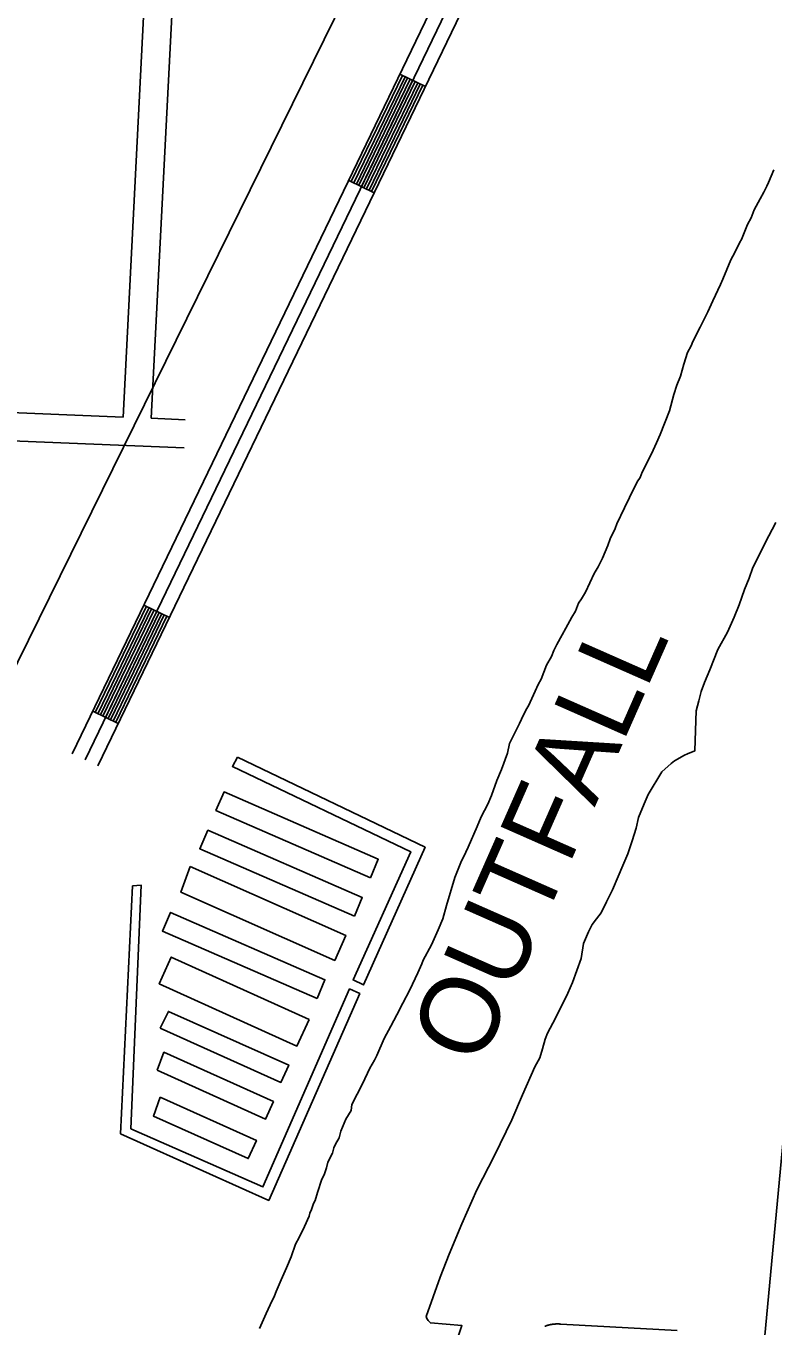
# Model space of a CAD drawing. Extents: x 3683402 to 3721514, y 487807 to 513565.
# Drawn here: x 3696820 to 3697613, y 500906 to 502284 of the extents above; entities that cross this region are included whole.
import ezdxf

# ---------------------------------------------------------------- set-up
doc = ezdxf.new("R2010")
doc.units = 0
for name, color, linetype in [('V-BLDG-OTLN', 7, 'Continuous'), ('V-RIVR-IDEN', 7, 'Continuous'), ('V-ROAD-CNTR', 7, 'Continuous'), ('V-TOPO-BNDY', 7, 'Continuous'), ('V-TOPO-SHOR', 7, 'Continuous')]:
    doc.layers.add(name, color=color, linetype=linetype)

msp = doc.modelspace()

# ---------------------------------------------------------------- linework, layer by layer
at = {"layer": 'V-BLDG-OTLN'}
for points in [[(3697044.7, 501508.9), (3697243.8, 501413.3), (3697178.5, 501267.3), (3697167.5, 501272.5), (3697228.6, 501408.5), (3697039.5, 501499)], [(3697185.9, 501380.9), (3697021.9, 501452.4), (3697030.5, 501472), (3697194.2, 501400.6)], [(3697168.9, 501340.2), (3697004.8, 501411.7), (3697013.4, 501431.3), (3697177.1, 501359.9)], [(3696994.7, 501392.9), (3697159.7, 501319.7), (3697147.9, 501293.2), (3696984.8, 501365.6)], [(3696933.5, 501372.3), (3696942.8, 501372.9), (3696931.8, 501114.8), (3697071.7, 501053.1), (3697163.8, 501263), (3697174.5, 501258), (3697078, 501038.7), (3696920.8, 501109.4)], [(3697129.3, 501252.9), (3696965.2, 501324.4), (3696973.8, 501344.1), (3697137.6, 501272.7)], [(3697120.8, 501230.5), (3697107.8, 501202.4), (3696961.8, 501268.5), (3696974.6, 501296.8)], [(3696962.7, 501221.3), (3696971.6, 501239.2), (3697099.1, 501182.2), (3697090.9, 501163.9)], [(3696959.5, 501176.7), (3696966.7, 501195.9), (3697082.9, 501143.6), (3697074.6, 501124.9)], [(3696962.8, 501148.1), (3697064.9, 501102.3), (3697056.3, 501083.1), (3696955.7, 501128.2)]]:
    msp.add_lwpolyline(points, close=True, dxfattribs=at)
at = {"layer": 'V-ROAD-CNTR'}
for p, q in [((3697217, 502233.1), (3697244.1, 502220.1)), ((3697162.8, 502120.5), (3697189.8, 502107.5)), ((3696945.6, 501670.1), (3696972.6, 501657.1)), ((3696891.3, 501557.5), (3696918.3, 501544.5))]:
    msp.add_line(p, q, dxfattribs=at)
for points in [[(3696869.6, 501512.5), (3697877.2, 503602.1)], [(3697897, 503608.5), (3696883.1, 501506)], [(3696896.6, 501499.5), (3697901.8, 503584.1)], [(3696980.5, 502990.5), (3696923.4, 501869.4)], [(3696977.2, 502337.1), (3696953.4, 501868.2)], [(3697165.5, 502119.2), (3697219.7, 502231.8)], [(3697168.2, 502117.9), (3697222.5, 502230.5)], [(3697170.9, 502116.6), (3697225.2, 502229.2)], [(3697173.6, 502115.3), (3697227.9, 502227.9)], [(3697176.3, 502114), (3697230.6, 502226.6)], [(3697179, 502112.7), (3697233.3, 502225.3)], [(3697181.7, 502111.4), (3697236, 502224)], [(3697184.4, 502110.1), (3697238.7, 502222.7)], [(3697187.1, 502108.8), (3697241.4, 502221.4)], [(3696923.4, 501869.4), (3696693, 501878.8)], [(3696989.4, 501866.7), (3696953.4, 501868.2)], [(3696988.2, 501836.8), (3696691.5, 501848.9)], [(3697685, 501758.1), (3697582.8, 500665.8)], [(3696894, 501556.2), (3696948.3, 501668.8)], [(3696896.7, 501554.9), (3696951, 501667.5)], [(3696899.4, 501553.6), (3696953.7, 501666.2)], [(3696902.1, 501552.3), (3696956.4, 501664.9)], [(3696904.8, 501551), (3696959.1, 501663.6)], [(3696907.5, 501549.7), (3696961.8, 501662.3)], [(3696910.2, 501548.4), (3696964.5, 501661)], [(3696912.9, 501547.1), (3696967.2, 501659.7)], [(3696915.6, 501545.8), (3696969.9, 501658.4)], [(3697370.7, 500905.3), (3697371.4, 500905.5), (3697372.1, 500905.8), (3697372.7, 500906), (3697373.4, 500906.2), (3697374.1, 500906.4), (3697374.8, 500906.5), (3697375.5, 500906.7), (3697376.2, 500906.8), (3697376.9, 500907), (3697377.6, 500907.1), (3697378.2, 500907.2), (3697378.9, 500907.3), (3697379.7, 500907.4), (3697380.4, 500907.5), (3697381.1, 500907.6), (3697381.8, 500907.6), (3697382.5, 500907.7), (3697383.2, 500907.7), (3697383.9, 500907.7), (3697384.6, 500907.7), (3697385.3, 500907.7), (3697386.1, 500907.7), (3697386.7, 500907.6), (3697387.4, 500907.6), (3697387.8, 500907.6), (3697511.2, 500900.9)]]:
    msp.add_lwpolyline(points, dxfattribs=at)
at = {"layer": 'V-TOPO-BNDY'}
msp.add_line((3697199.9, 502398), (3695552.8, 499054.3), dxfattribs=at)
at = {"layer": 'V-TOPO-SHOR'}
for points in [[(3697331.1, 501513), (3697333.5, 501523.2), (3697343.8, 501544.4), (3697346.2, 501549.1), (3697351, 501559.3), (3697353.4, 501563.2), (3697360.5, 501578.9), (3697363.7, 501586), (3697366.9, 501591.4), (3697372.5, 501606.3), (3697378, 501615.7), (3697380.4, 501622), (3697383.6, 501628.3), (3697389.2, 501638.5), (3697393.1, 501645.5), (3697399.5, 501657.3), (3697403.4, 501663.6), (3697406.6, 501672.2), (3697409.8, 501676.9), (3697413.8, 501683.9), (3697423.3, 501703.5), (3697427.3, 501710.6), (3697432.1, 501720), (3697437.6, 501733.3), (3697440, 501740.4), (3697445.6, 501751.4), (3697447.2, 501756.1), (3697455.2, 501773.3), (3697460.7, 501784.3), (3697468.7, 501800.8), (3697471.8, 501805.5), (3697474.2, 501811), (3697483.8, 501830.6), (3697489.3, 501842.3), (3697493.3, 501850.9), (3697502.9, 501876), (3697507.7, 501893.3), (3697510.9, 501903.5), (3697514.9, 501912.9), (3697518.1, 501925.5), (3697522.1, 501938), (3697526.1, 501945.1), (3697527.7, 501949.8), (3697535.6, 501964.7), (3697543.6, 501981.2), (3697549.2, 501992.9), (3697557.1, 502010.2), (3697559.5, 502015.7), (3697568.3, 502036.1), (3697572.2, 502043.9), (3697577.8, 502054.9), (3697579.4, 502058), (3697585.8, 502073.7), (3697589.7, 502080.7), (3697592.9, 502089.4), (3697599.3, 502101.1), (3697603.3, 502108.2), (3697606.4, 502114.5), (3697608, 502118.4), (3697613.6, 502131.7)], [(3697613.6, 502131.7), (3697608, 502118.4), (3697606.4, 502114.5), (3697603.3, 502108.2), (3697599.3, 502101.1), (3697592.9, 502089.4), (3697589.7, 502080.7), (3697585.8, 502073.7), (3697579.4, 502058), (3697577.8, 502054.9), (3697572.2, 502043.9), (3697568.3, 502036.1), (3697559.5, 502015.7), (3697557.1, 502010.2), (3697549.2, 501992.9), (3697543.6, 501981.2), (3697535.6, 501964.7), (3697527.7, 501949.8), (3697526.1, 501945.1), (3697522.1, 501938), (3697518.1, 501925.5), (3697514.9, 501912.9), (3697510.9, 501903.5), (3697507.7, 501893.3), (3697502.9, 501876), (3697493.3, 501850.9), (3697489.3, 501842.3), (3697483.8, 501830.6), (3697474.2, 501811), (3697471.8, 501805.5), (3697468.7, 501800.8), (3697460.7, 501784.3), (3697455.2, 501773.3), (3697447.2, 501756.1), (3697445.6, 501751.4), (3697440, 501740.4)], [(3697615.8, 501757.8), (3697604.4, 501736.1), (3697598.2, 501723.2), (3697591.3, 501709.8), (3697587.4, 501698.8), (3697582.7, 501686.6), (3697576.9, 501670.3), (3697571.7, 501657.3), (3697564.6, 501641.3), (3697554.4, 501623), (3697546, 501601.5)], [(3697440, 501740.4), (3697437.6, 501733.3), (3697432.1, 501720), (3697427.3, 501710.6), (3697423.3, 501703.5), (3697413.8, 501683.9), (3697409.8, 501676.9), (3697406.6, 501672.2), (3697403.4, 501663.6), (3697399.5, 501657.3), (3697393.1, 501645.5), (3697389.2, 501638.5), (3697383.6, 501628.3), (3697380.4, 501622), (3697378, 501615.7), (3697372.5, 501606.3), (3697366.9, 501591.4), (3697363.7, 501586), (3697360.5, 501578.9), (3697353.4, 501563.2), (3697351, 501559.3), (3697346.2, 501549.1), (3697343.8, 501544.4), (3697333.5, 501523.2), (3697331.1, 501513), (3697324.7, 501495.8), (3697319.9, 501484), (3697314.3, 501468.3), (3697310.3, 501458.9), (3697303.2, 501445.6), (3697299.2, 501435.4), (3697289.6, 501413.4), (3697287.2, 501407.9), (3697281.7, 501397), (3697275.3, 501381.3), (3697266.5, 501351.4), (3697262.5, 501337.3), (3697257.7, 501325.6), (3697250.5, 501309.9), (3697241.8, 501293.4), (3697240.2, 501289.5), (3697236.2, 501280.1), (3697227.5, 501262), (3697220.3, 501247.9), (3697213.9, 501235.4), (3697207.6, 501223.6), (3697200.4, 501210.3), (3697192.5, 501192.3), (3697190.1, 501187.6), (3697185.3, 501178.9), (3697177.4, 501162.5), (3697166.2, 501140.5), (3697165.4, 501134.2), (3697159.9, 501124.8), (3697154.3, 501112.3), (3697152.7, 501105.2), (3697148.7, 501098.2), (3697147.1, 501094.3), (3697145.5, 501088.8), (3697140.7, 501079.4), (3697139.1, 501073.1), (3697136.7, 501066), (3697134.4, 501061.3), (3697129.6, 501047.2), (3697127.1, 501038.6), (3697125.6, 501035.4), (3697123.2, 501029.1), (3697121.6, 501025.2), (3697120.8, 501022.1), (3697116, 501011.1), (3697110.4, 500999.3), (3697106.4, 500992.3), (3697101.7, 500979), (3697096.9, 500967.2), (3697091.3, 500954.6), (3697085.7, 500942.1), (3697084.1, 500937.4), (3697079.4, 500928), (3697075.4, 500918.6), (3697068.2, 500902.9)], [(3697546, 501601.5), (3697540.3, 501587.9), (3697536.8, 501578.4), (3697534.1, 501568.6), (3697531.4, 501558.1), (3697531.1, 501547.6), (3697530.1, 501515.6), (3697522.1, 501512.5), (3697518.9, 501511), (3697508.3, 501505), (3697504.9, 501502.1), (3697495.1, 501493.1), (3697480.5, 501469.2), (3697476.3, 501459.2), (3697470.1, 501444.9), (3697467.6, 501433.4), (3697463.6, 501420.2), (3697458.9, 501406.3), (3697453.5, 501393.9), (3697448.5, 501382.2), (3697442.6, 501368.1), (3697436.2, 501355.4), (3697430.7, 501343.7), (3697425.8, 501337.4), (3697420.9, 501331.5), (3697417.2, 501323.7), (3697412, 501311.3), (3697409.2, 501295.4), (3697400.2, 501269.8), (3697395.1, 501258.4), (3697389.6, 501246.9), (3697379.2, 501226.7), (3697373.8, 501216.2), (3697371.3, 501209.6), (3697368.3, 501199.4), (3697365.6, 501190.1), (3697360.2, 501180.4), (3697347.3, 501150.7), (3697335.7, 501124.1), (3697317.4, 501086.3), (3697298.8, 501050), (3697282.8, 501013.7), (3697269.4, 500981.8), (3697259.7, 500957.2), (3697245.1, 500915.5), (3697245.8, 500913.3), (3697247, 500911.3), (3697249.4, 500908.8), (3697282.9, 500906), (3697278.2, 500892.3)], [(3697068.2, 500902.9), (3697075.4, 500918.6), (3697079.4, 500928), (3697084.1, 500937.4), (3697085.7, 500942.1), (3697091.3, 500954.6), (3697096.9, 500967.2), (3697101.7, 500979), (3697106.4, 500992.3), (3697110.4, 500999.3), (3697116, 501011.1), (3697120.8, 501022.1), (3697121.6, 501025.2), (3697123.2, 501029.1), (3697125.6, 501035.4), (3697127.1, 501038.6), (3697129.6, 501047.2), (3697134.4, 501061.3), (3697136.7, 501066), (3697139.1, 501073.1), (3697140.7, 501079.4), (3697145.5, 501088.8), (3697147.1, 501094.3), (3697148.7, 501098.2), (3697152.7, 501105.2), (3697154.3, 501112.3), (3697159.9, 501124.8), (3697165.4, 501134.2), (3697166.2, 501140.5), (3697177.4, 501162.5), (3697185.3, 501178.9), (3697190.1, 501187.6), (3697192.5, 501192.3), (3697200.4, 501210.3), (3697207.6, 501223.6), (3697213.9, 501235.4), (3697220.3, 501247.9), (3697227.5, 501262), (3697236.2, 501280.1), (3697240.2, 501289.5), (3697241.8, 501293.4), (3697250.5, 501309.9), (3697257.7, 501325.6), (3697262.5, 501337.3), (3697266.5, 501351.4), (3697275.3, 501381.3), (3697281.7, 501397), (3697287.2, 501407.9), (3697289.6, 501413.4), (3697299.2, 501435.4), (3697303.2, 501445.6), (3697310.3, 501458.9), (3697314.3, 501468.3), (3697319.9, 501484), (3697324.7, 501495.8), (3697331.1, 501513)], [(3697136.5, 500684.7), (3697149.6, 500710.3), (3697166.7, 500751), (3697168.5, 500758.5), (3697174.4, 500772.2), (3697181.1, 500785.6), (3697211.2, 500847.2), (3697221.8, 500866.7), (3697230.2, 500877.4), (3697233.4, 500882.1), (3697237.9, 500892.3), (3697278.2, 500892.3), (3697282.9, 500906), (3697249.4, 500908.8), (3697247, 500911.3), (3697245.8, 500913.3), (3697245.1, 500915.5)]]:
    msp.add_lwpolyline(points, dxfattribs=at)

# ---------------------------------------------------------------- texts
at = {"layer": 'V-RIVR-IDEN'}
msp.add_text('OUTFALL', height=83, rotation=66.1908, dxfattribs=at).set_placement((3697301.7, 501178.9))

doc.saveas('drawing.dxf')
